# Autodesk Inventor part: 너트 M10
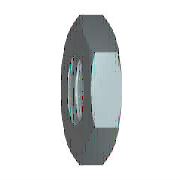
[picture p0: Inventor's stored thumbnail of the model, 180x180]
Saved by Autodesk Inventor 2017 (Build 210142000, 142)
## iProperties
IsCustomPart: 1
Created: 2012-02
Part Number: 너트 M10
Material: 스테인리스강
Description: 미터법 정밀 피치 스레드가 있는 6각 가는 너트(모따기됨)
Document SubType Name: Modeling
Standard: ISO 8675
Designer: mduedu
Standard Revision: Second edition 1999-08-15
Standards Organization: ISO
Language: ko-KR
Size Designation: M10 x 1
Categories: <MemberInstance><Categories><Category DisplayName="조임쇠" InternalName="e4da775c-781d-43d5-af7c-5136215cf5a6" Mnemonic="FSTN"><Category DisplayName="너트" InternalN
Density: 8.08 g/cm^3
Appearance: 기본값
Author: mduedu
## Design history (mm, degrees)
sketch "스케치1"
  geometry: L1 (-9.238, 0)-(-4.619, 8); L2 (-4.619, 8)-(4.619, 8); L3 (4.619, 8)-(9.238, 0); L4 (9.238, 0)-(4.619, -8); L5 (4.619, -8)-(-4.619, -8); L6 (-4.619, -8)-(-9.238, 0); 2 further points
  constraints: 12 end point, 1 coincident, 1 horizontal, 11 other
  dimensions: "d0" = 18.47521 distance of L3.end L1.start (= 1.1547 x SW)
extrude "본체" new body sketch "스케치1" distance "d1" = 5 (= KOH); taper "d2" = 0 deg
sketch "스케치2"
  geometry: L1 (0, 4.619)-(0, 9.238) reference; L2 (0, 9.238)-(5, 9.238) reference; L3 (5, 4.619)-(5, 9.238) reference; L4 (-1, 0)-(6, 0) reference; L5 (1.11, 9.238)-(0, 7.315); L6 (3.89, 9.238)-(5, 7.315)
  constraints: 4 end point, 4 point on line
  dimensions: "d3" = 30 deg angle of L1 L5 (= ANG1); "d4" = 30 deg angle of L3 L6 (= ANG2); "d5" = 14.63 diameter of L5.end L4 (= SW0); "d6" = 14.63 diameter of L6.end L4 (= SW01)
revolve "모따기1" sketch "스케치2" stored, may be unused: angle "d7" = 90 deg
sketch "스케치3"
  geometry: 4 further points
  constraints: 1 coincident, 1 other
hole "스레드" sketch "스케치3" at (0, 0) diameter "d25" = 8.91747; stored, may be unused: countersink angle "d29" = 82 deg, drill point angle "d31" = 118 deg; dims "d26" = 6, "d27" = 4, "d28" = 2, "d30" = 8
workaxis "Work Axis1"
workplane "Work Plane1"
body "Solid1"
chamfer "모따기2" distance "d8" = 0.54127 (= -0.5 x GD1 + 0.5 x NND); stored, may be unused: angle "d9" = 30 deg, second distance "d40" = 0.54127 (= -0.5 x GD1 + 0.5 x NND)
chamfer "모따기3" distance "d10" = 0.54127 (= -0.5 x GD1 + 0.5 x NND); stored, may be unused: angle "d11" = 30 deg, second distance "d41" = 0.54127 (= -0.5 x GD1 + 0.5 x NND)
other parameters: "ANG1" = 30 deg [user parameter; used in 1 equation term], "ANG2" = 30 deg [user parameter; used in 1 equation term], "KOH" = 5 [user parameter; used in 1 equation term], "SW" = 16 [user parameter; used in 1 equation term], "SW0" = 14.63 [user parameter; used in 2 equation terms], "SW01" = 14.63 (= SW0) [user parameter; used in 1 equation term], "GD1" = 8.91747 (computed from THREADDIA, PTC, TOA) [user parameter; used in 4 equation terms], "d13" = 0, "d14" = 0, "d39" = 0, "d42" = 0, "GUL" = 0.54127 (= 0.541266 x PTC) [user parameter], "TOA" = 30 deg [user parameter; used in 1 equation term], "PTC" = 1 [user parameter; used in 4 equation terms], "E0" = 17.77 [user parameter], "GAL" = 0.54127 (= 0.541266 x PTC) [user parameter]
